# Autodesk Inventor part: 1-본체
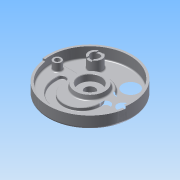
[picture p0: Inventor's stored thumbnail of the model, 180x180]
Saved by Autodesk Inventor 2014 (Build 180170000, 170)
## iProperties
Created: 2015-06
Part Number: 1-본체
Material: 알루미늄 6061
Document SubType Name: Modeling
Designer: Administrator
Density: 2.71 g/cm^3
Appearance: 알루미늄 - 평지
Mass: 1070.29 g
Surface Area: 1033.58 cm^2
Volume: 394.94 cm^3
Author: Administrator
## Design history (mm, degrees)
sketch "스케치1"
  geometry: C1 r 95 at (0, 0); 1 further point
  constraints: 1 centre point, 1 coincident
  dimensions: "d0" = 190 diameter of C1
extrude "돌출1" new body sketch "스케치1" distance "d1" = 32; taper "d2" = 0 deg
sketch "스케치2"
  geometry: L1 (-38.833, 16)-(-88.566, 16); L2 (38.833, 16)-(88.566, 16); C1 r 95 at (0, 0) reference; A1 r 90 centre (0, 0) between (-88.566, 16) and (88.566, 16); A2 r 42 centre (0, 0) between (-38.833, 16) and (38.833, 16)
  constraints: 4 end point, 4 point on circle, 2 centre point, 2 coincident, 2 collinear, 1 horizontal
  dimensions: "d3" = 180 diameter of A1; "d4" = 84 diameter of A2; "d5" = 16 distance from line of L2 C1.centre
extrude "돌출2" cut sketch "스케치2" distance "d6" = 25; taper "d7" = 0 deg
extrude "돌출3" cut sketch "스케치2" distance "d8" = 18; taper "d9" = 0 deg
sketch "스케치3"
  geometry: C1 r 35 at (0, 0); A1 r 90 centre (0, 0) between (-88.566, 16) and (88.566, 16) reference
  constraints: 1 centre point, 1 coincident
  dimensions: "d10" = 70 diameter of C1
extrude "돌출4" join sketch "스케치3" distance "d11" = 10; taper "d12" = -10 deg
sketch "스케치4"
  geometry: L1 (38.833, 16)-(88.566, 16) reference; L2 (41, -19)-(59, -19); L3 (-59, -19)-(-41, -19); L4 (-59, -19)-(-59, -14); L5 (-41, -14)-(-41, -19); L6 (41, -19)-(41, -14); L7 (59, -14)-(59, -19); C1 r 35 at (0, 0) reference; A1 r 41 centre (0, -19) between (-41, -19) and (41, -19); A2 r 59 centre (0, -19) between (-59, -19) and (59, -19); A3 r 9 centre (-50, -14) between (-41, -14) and (-59, -14); A4 r 9 centre (50, -14) between (59, -14) and (41, -14)
  constraints: 12 end point, 9 point on circle, 8 tangent, 4 centre point, 4 parallel, 3 horizontal alignment, 1 coincident, 1 collinear, 1 perpendicular, 1 vertical alignment
  dimensions: "d15" = 59 radius of A2; "d16" = 41 radius of A1; "d17" = 19 distance of A2.centre C1.centre; "d18" = 5 vertical distance of L2.end A4.centre
extrude "돌출5" cut sketch "스케치4" distance "d19" = 7; taper "d20" = 0 deg
sketch "스케치5"
  geometry: C1 r 35 at (0, 0) reference; C2 r 9 at (-74, 0); C3 r 9 at (74, 0)
  constraints: 2 centre point, 2 horizontal alignment, 1 equal radius
  dimensions: "d21" = 18 diameter of C2; "d22" = 74 distance of C1.centre C2.centre; "d23" = 74 distance of C1.centre C3.centre (= d22)
extrude "돌출6" join sketch "스케치5" distance "d24" = 18; taper "d25" = 0 deg
sketch "스케치6"
  geometry: C1 r 15 at (-40, 52); C2 r 15 at (40, 52); A1 r 42 centre (0, 0) between (38.833, 16) and (-38.833, 16) reference
  constraints: 2 centre point, 1 equal radius, 1 horizontal alignment
  dimensions: "d26" = 30 diameter of C1; "d27" = 40 horizontal distance of A1.centre C1.centre; "d28" = 40 horizontal distance of A1.centre C2.centre (= d27); "d29" = 52 vertical distance of C2.centre A1.centre
extrude "돌출7" join sketch "스케치6" distance "d30" = 25; taper "d31" = 0 deg
hole "구멍1" diameter "d34" = 20; stored, may be unused: countersink angle "d38" = 90 deg, drill point angle "d40" = 118 deg; dims "d32" = 10, "d33" = 10, "d35" = 6, "d36" = 4, "d37" = 2, "d39" = 8
hole "구멍2" diameter "d43" = 20; stored, may be unused: countersink angle "d47" = 90 deg, drill point angle "d49" = 118 deg; dims "d41" = 10, "d42" = 10, "d44" = 6, "d45" = 4, "d46" = 2, "d48" = 8
sketch "스케치7"
  geometry: C1 r 9 at (-74, 0) reference; C2 r 9 at (74, 0) reference; 2 further points
  constraints: 2 coincident
hole "구멍3" sketch "스케치7" at (-74, 0), (74, 0) diameter "d50" = 11; stored, may be unused: countersink angle "d54" = 90 deg, drill point angle "d56" = 118 deg; dims "d51" = 6, "d52" = 18, "d53" = 11, "d55" = 8
sketch "스케치8"
  geometry: C1 r 95 at (0, 0) reference; C2 r 26 at (0, 0)
  constraints: 1 centre point, 1 coincident
  dimensions: "d57" = 52 diameter of C2
extrude "돌출8" join sketch "스케치8" distance "d58" = 12; taper "d59" = -15 deg
hole "구멍4" diameter "d62" = 23; stored, may be unused: countersink angle "d66" = 90 deg, drill point angle "d68" = 118 deg; dims "d60" = 10, "d61" = 10, "d63" = 6, "d64" = 50, "d65" = 15, "d67" = 8
sketch "스케치9"
  geometry: C1 r 95 at (0, 0) reference; C2 r 68 at (0, 0)
  constraints: 1 centre point, 1 coincident, 1 other
  dimensions: "d69" = 136 diameter of C2
feature "엠보싱1" sketch "스케치9" dims "d70" = 0.5, "d71" = 0
sketch "스케치10"
  geometry: L1 (0, 0)-(-95, 0); L2 (0, 0)-(95, 0); L3 (0, 0)-(89.124, -12.526); L4 (0, 0)-(-89.124, -12.526); L5 (-89.124, -12.526)-(-94.075, -13.221); L6 (89.124, -12.526)-(94.075, -13.221); A1 r 95 centre (0, 0) between (-95, 0) and (95, 0) reference; A2 r 90 centre (0, 0) between (89.124, -12.526) and (-89.124, -12.526) reference
  constraints: 12 end point, 6 point on circle, 3 collinear, 1 horizontal
  dimensions: "d72" = 8 deg angle of L3 L2; "d73" = 8 deg angle of L1 L4
extrude "돌출9" cut sketch "스케치10" distance "d74" = 5; taper "d75" = 0 deg
sketch "스케치11"
  geometry: L1 (-6, -19)-(6, -19); L2 (6, -19)-(6, 19); L3 (6, 19)-(-6, 19); L4 (-6, 19)-(-6, -19); L5 (-6, -19)-(6, 19); L6 (6, -19)-(-6, 19); L7 (99, 6)-(61, 6); L8 (61, 6)-(61, -6); L9 (61, -6)-(99, -6); L10 (99, -6)-(99, 6); L11 (99, 6)-(61, -6); L12 (61, 6)-(99, -6); C1 r 15 at (0, 0) reference; C2 r 10 at (80, 0) reference; C3 r 15 at (80, 0) reference; 1 further point
  constraints: 24 end point, 4 midpoint, 4 parallel, 2 horizontal, 2 perpendicular
  dimensions: "d86" = 12 distance of L7.end L8.end; "d87" = 38 distance of L7.start L7.end; "d88" = 38 distance of L1.end L2.end; "d89" = 12 distance of L2.end L3.end
extrude "돌출10" cut sketch "스케치11" distance "d90" = 3; taper "d91" = 0 deg
chamfer "모따기1" distance "d76" = 1; stored, may be unused: second distance "d77" = 2, angle "d78" = 45 deg
fillet "모깎기1" dims "d79" = 0.3, "d80" = 10, "d81" = 5, "d85" = 1
fillet "모깎기2" dims "d82" = 3, "d83" = 3, "d84" = 3, "d92" = 2
node "솔리드1"
node "투영된 루프1"
